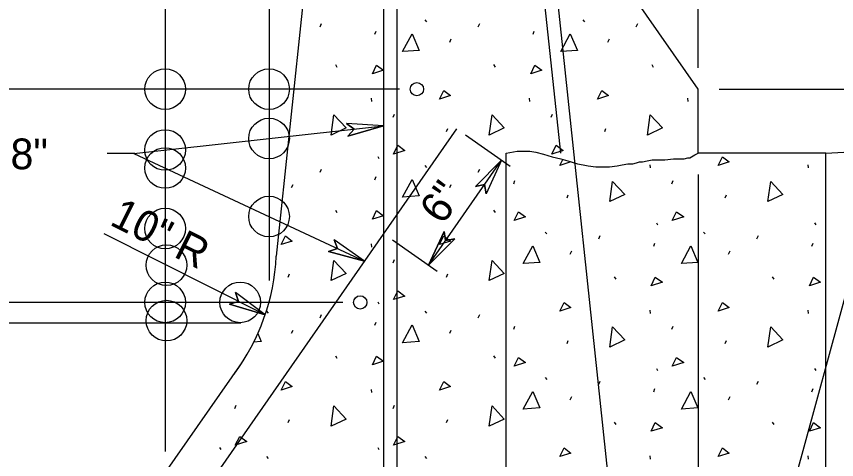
# Model space of a CAD drawing. Extents: x -26.46 to -19.21, y -3.62 to 6.25.
# Drawn here: x -23.781 to -22.178, y 2.816 to 3.682 of the extents above; entities that cross this region are included whole.
import ezdxf

# ---------------------------------------------------------------- set-up
doc = ezdxf.new("R2010")
doc.units = 0
for name, color, linetype in [('ANNO-WOUT', 7, 'Continuous'), ('DETL-DIMS', 7, 'Continuous'), ('DETL-PATT', 7, 'Continuous'), ('Level 10', 7, 'Continuous'), ('Level 12', 7, 'Continuous'), ('SECT-GRND_P', 7, 'Continuous'), ('SUBS-FOOT_P', 7, 'Continuous'), ('SUPR-PARA_P', 7, 'Continuous'), ('SUPR-RFRC', 7, 'Continuous')]:
    doc.layers.add(name, color=color, linetype=linetype)

msp = doc.modelspace()

# ---------------------------------------------------------------- linework, layer by layer
at = {"layer": 'ANNO-WOUT'}
for centre in [(-23.4904, 3.5396), (-23.2873, 3.5396), (-23.2873, 3.4431), (-23.4904, 3.4207), (-23.4904, 3.3855), (-23.2873, 3.2906), (-23.4904, 3.2672), (-23.4878, 3.1956), (-23.4904, 3.1229), (-23.3437, 3.1229), (-23.4878, 3.0872)]:
    msp.add_circle(centre, 0.0397, dxfattribs=at)
at = {"layer": 'DETL-DIMS'}
for p, q in [((-23.0634, 3.4678), (-23.1358, 3.4726)), ((-23.121, 3.4615), (-23.1358, 3.4726)), ((-23.0634, 3.4678), (-23.133, 3.4475)), ((-23.133, 3.4475), (-23.121, 3.4615)), ((-22.8327, 3.4011), (-22.8838, 3.3495)), ((-22.8327, 3.4011), (-22.8632, 3.3351)), ((-22.8838, 3.3495), (-22.8659, 3.3535)), ((-22.8659, 3.3535), (-22.8632, 3.3351)), ((-22.9756, 3.1959), (-22.945, 3.2617)), ((-22.945, 3.2617), (-22.9425, 3.2435)), ((-23.1007, 3.2034), (-23.1601, 3.2452)), ((-23.1533, 3.2279), (-23.1601, 3.2452)), ((-22.9756, 3.1959), (-22.9243, 3.2473)), ((-22.9425, 3.2435), (-22.9243, 3.2473)), ((-23.1708, 3.2223), (-23.1533, 3.2279)), ((-23.1007, 3.2034), (-23.1708, 3.2223)), ((-23.295, 3.0984), (-23.3531, 3.1419)), ((-23.3468, 3.1245), (-23.3531, 3.1419)), ((-23.3645, 3.1194), (-23.3468, 3.1245)), ((-23.295, 3.0984), (-23.3645, 3.1194))]:
    msp.add_line(p, q, dxfattribs=at)
for points in [[(-23.133, 3.4475), (-23.0634, 3.4678), (-23.1358, 3.4726), (-23.121, 3.4615)], [(-22.8838, 3.3495), (-22.8327, 3.4011), (-22.8632, 3.3351), (-22.8659, 3.3535)], [(-22.945, 3.2617), (-22.9756, 3.1959), (-22.9243, 3.2473), (-22.9425, 3.2435)], [(-23.1708, 3.2223), (-23.1007, 3.2034), (-23.1601, 3.2452), (-23.1533, 3.2279)], [(-23.3645, 3.1194), (-23.295, 3.0984), (-23.3531, 3.1419), (-23.3468, 3.1245)]]:
    msp.add_lwpolyline(points, close=True, dxfattribs=at)
at = {"layer": 'DETL-PATT'}
for p, q in [((-22.9829, 3.6748), (-22.9798, 3.6709)), ((-22.6737, 3.6748), (-22.6706, 3.6709)), ((-23.1877, 3.6617), (-23.1847, 3.6678)), ((-22.8786, 3.6617), (-22.8755, 3.6678)), ((-22.5694, 3.6617), (-22.5663, 3.6678)), ((-23.0803, 3.647), (-23.078, 3.6532)), ((-22.7711, 3.647), (-22.7688, 3.6532)), ((-22.9342, 3.6315), (-22.9311, 3.6377)), ((-22.625, 3.6315), (-22.622, 3.6377)), ((-23.1576, 3.5875), (-23.1545, 3.5828)), ((-22.8484, 3.5875), (-22.8453, 3.5828)), ((-22.5392, 3.5875), (-22.5362, 3.5828)), ((-23.088, 3.5218), (-23.0873, 3.5156)), ((-22.7789, 3.5218), (-22.7781, 3.5156)), ((-22.4697, 3.5218), (-22.4689, 3.5156)), ((-23.0447, 3.4847), (-23.0424, 3.4908)), ((-22.7356, 3.4847), (-22.7333, 3.4908)), ((-22.9404, 3.4568), (-22.9381, 3.463)), ((-22.6312, 3.4568), (-22.6289, 3.463)), ((-23.0749, 3.4081), (-23.0726, 3.4043)), ((-22.7187, 3.3903), (-22.7128, 3.4022)), ((-23.1877, 3.3772), (-23.1847, 3.3834)), ((-22.9829, 3.3904), (-22.9798, 3.3865)), ((-22.8786, 3.3772), (-22.8755, 3.3834)), ((-22.5432, 3.3918), (-22.5425, 3.3857)), ((-22.2341, 3.3918), (-22.2333, 3.3857)), ((-23.0803, 3.3625), (-23.078, 3.3687)), ((-23.2434, 3.3471), (-23.2403, 3.3533)), ((-22.9342, 3.3471), (-22.9311, 3.3533)), ((-22.8091, 3.3547), (-22.8068, 3.3609)), ((-22.5, 3.3547), (-22.4976, 3.3609)), ((-22.7048, 3.3269), (-22.7025, 3.3331)), ((-22.3956, 3.3269), (-22.3933, 3.3331)), ((-23.1576, 3.303), (-23.1545, 3.2984)), ((-22.8484, 3.303), (-22.8453, 3.2984)), ((-22.5301, 3.2782), (-22.5278, 3.2744)), ((-22.2209, 3.2782), (-22.2186, 3.2744)), ((-22.7473, 3.2604), (-22.7442, 3.2566)), ((-22.4381, 3.2604), (-22.435, 3.2566)), ((-22.643, 3.2473), (-22.6399, 3.2535)), ((-22.5355, 3.2326), (-22.5332, 3.2388)), ((-22.3338, 3.2473), (-22.3307, 3.2535)), ((-22.2263, 3.2326), (-22.224, 3.2388)), ((-23.088, 3.2373), (-23.0873, 3.2311)), ((-22.6986, 3.2172), (-22.6955, 3.2233)), ((-22.3894, 3.2172), (-22.3863, 3.2233)), ((-23.0447, 3.2002), (-23.0424, 3.2064)), ((-23.2496, 3.1724), (-23.2473, 3.1786)), ((-22.9404, 3.1724), (-22.9381, 3.1786)), ((-22.6128, 3.1731), (-22.6097, 3.1685)), ((-22.3036, 3.1731), (-22.3005, 3.1685)), ((-23.0749, 3.1237), (-23.0726, 3.1198)), ((-23.2921, 3.1059), (-23.289, 3.1021)), ((-23.1877, 3.0928), (-23.1847, 3.099)), ((-22.9829, 3.1059), (-22.9798, 3.1021)), ((-22.8786, 3.0928), (-22.8755, 3.099)), ((-22.5432, 3.1074), (-22.5425, 3.1012)), ((-22.2341, 3.1074), (-22.2333, 3.1012)), ((-23.0803, 3.0781), (-23.078, 3.0843)), ((-23.2434, 3.0626), (-23.2403, 3.0688)), ((-22.9342, 3.0626), (-22.9311, 3.0688)), ((-22.8091, 3.0703), (-22.8068, 3.0765)), ((-22.5, 3.0703), (-22.4976, 3.0765)), ((-22.7048, 3.0425), (-22.7025, 3.0487)), ((-22.3956, 3.0425), (-22.3933, 3.0487)), ((-23.1576, 3.0186), (-23.1545, 3.0139)), ((-22.8484, 3.0186), (-22.8453, 3.0139)), ((-22.5301, 2.9938), (-22.5278, 2.9899)), ((-22.2209, 2.9938), (-22.2186, 2.9899)), ((-22.7473, 2.976), (-22.7442, 2.9721)), ((-22.643, 2.9629), (-22.6399, 2.9691)), ((-22.4381, 2.976), (-22.435, 2.9721)), ((-22.3338, 2.9629), (-22.3307, 2.9691)), ((-23.088, 2.9529), (-23.0873, 2.9467)), ((-22.5355, 2.9482), (-22.5332, 2.9544)), ((-22.2263, 2.9482), (-22.224, 2.9544)), ((-22.6986, 2.9327), (-22.6955, 2.9389)), ((-22.3894, 2.9327), (-22.3863, 2.9389)), ((-23.3539, 2.9158), (-23.3516, 2.922)), ((-23.0447, 2.9158), (-23.0424, 2.922)), ((-23.2496, 2.8879), (-23.2473, 2.8941)), ((-22.9404, 2.8879), (-22.9381, 2.8941)), ((-22.6128, 2.8887), (-22.6097, 2.884)), ((-22.3036, 2.8887), (-22.3005, 2.884)), ((-23.3841, 2.8393), (-23.3818, 2.8354)), ((-23.0749, 2.8393), (-23.0726, 2.8354)), ((-22.5432, 2.823), (-22.5425, 2.8168)), ((-22.2341, 2.823), (-22.2333, 2.8168)), ((-23.2921, 2.8215), (-23.289, 2.8176)), ((-22.9829, 2.8215), (-22.9798, 2.8176))]:
    msp.add_line(p, q, dxfattribs=at)
for points in [[(-23.0262, 3.613), (-23.0076, 3.6477), (-22.9937, 3.6153), (-23.0262, 3.613)], [(-22.717, 3.613), (-22.6985, 3.6477), (-22.6846, 3.6153), (-22.717, 3.613)], [(-23.0849, 3.5697), (-23.0772, 3.5867), (-23.0633, 3.5766), (-23.0849, 3.5697)], [(-22.7758, 3.5697), (-22.768, 3.5867), (-22.7541, 3.5766), (-22.7758, 3.5697)], [(-22.9543, 3.5202), (-22.9458, 3.5372), (-22.9327, 3.5272), (-22.9543, 3.5202)], [(-22.6451, 3.5202), (-22.6366, 3.5372), (-22.6235, 3.5272), (-22.6451, 3.5202)], [(-23.1661, 3.4499), (-23.1607, 3.4893), (-23.1367, 3.4638), (-23.1661, 3.4499)], [(-22.8569, 3.4499), (-22.8515, 3.4893), (-22.8276, 3.4638), (-22.8569, 3.4499)], [(-22.5477, 3.4499), (-22.5423, 3.4893), (-22.5184, 3.4638), (-22.5477, 3.4499)], [(-23.044, 3.4128), (-23.0355, 3.4298), (-23.0216, 3.4197), (-23.044, 3.4128)], [(-22.7348, 3.4128), (-22.7263, 3.4298), (-22.7124, 3.4197), (-22.7348, 3.4128)], [(-22.4095, 3.3903), (-22.401, 3.4073), (-22.3879, 3.3973), (-22.4095, 3.3903)], [(-22.6977, 3.3978), (-22.6971, 3.3973), (-22.7187, 3.3903)], [(-23.0262, 3.3285), (-23.0076, 3.3633), (-22.9937, 3.3308), (-23.0262, 3.3285)], [(-22.6213, 3.32), (-22.6159, 3.3594), (-22.5919, 3.3339), (-22.6213, 3.32)], [(-22.3121, 3.32), (-22.3067, 3.3594), (-22.2828, 3.3339), (-22.3121, 3.32)], [(-23.0849, 3.2852), (-23.0772, 3.3022), (-23.0633, 3.2922), (-23.0849, 3.2852)], [(-22.8084, 3.2829), (-22.7999, 3.2999), (-22.786, 3.2898), (-22.8084, 3.2829)], [(-22.4992, 3.2829), (-22.4907, 3.2999), (-22.4768, 3.2898), (-22.4992, 3.2829)], [(-23.2635, 3.2358), (-23.255, 3.2528), (-23.2418, 3.2427), (-23.2635, 3.2358)], [(-22.9543, 3.2358), (-22.9458, 3.2528), (-22.9327, 3.2427), (-22.9543, 3.2358)], [(-22.7906, 3.1986), (-22.772, 3.2334), (-22.7581, 3.2009), (-22.7906, 3.1986)], [(-22.4814, 3.1986), (-22.4629, 3.2334), (-22.4489, 3.2009), (-22.4814, 3.1986)], [(-23.1661, 3.1654), (-23.1607, 3.2049), (-23.1367, 3.1793), (-23.1661, 3.1654)], [(-22.8569, 3.1654), (-22.8515, 3.2049), (-22.8276, 3.1793), (-22.8569, 3.1654)], [(-22.5402, 3.1553), (-22.5324, 3.1723), (-22.5185, 3.1623), (-22.5402, 3.1553)], [(-22.231, 3.1553), (-22.2233, 3.1723), (-22.2093, 3.1623), (-22.231, 3.1553)], [(-23.044, 3.1283), (-23.0355, 3.1453), (-23.0216, 3.1353), (-23.044, 3.1283)], [(-22.7187, 3.1059), (-22.7102, 3.1229), (-22.6971, 3.1128), (-22.7187, 3.1059)], [(-22.4095, 3.1059), (-22.401, 3.1229), (-22.3879, 3.1128), (-22.4095, 3.1059)], [(-23.0262, 3.0441), (-23.0076, 3.0789), (-22.9937, 3.0464), (-23.0262, 3.0441)], [(-22.6213, 3.0355), (-22.6159, 3.0749), (-22.5919, 3.0494), (-22.6213, 3.0355)], [(-22.3121, 3.0355), (-22.3067, 3.0749), (-22.2828, 3.0494), (-22.3121, 3.0355)], [(-23.3095, 3.0618), (-23.3029, 3.0464), (-23.3175, 3.0454)], [(-23.0849, 3.0008), (-23.0772, 3.0178), (-23.0633, 3.0078), (-23.0849, 3.0008)], [(-22.8084, 2.9984), (-22.7999, 3.0154), (-22.786, 3.0054), (-22.8084, 2.9984)], [(-22.4992, 2.9984), (-22.4907, 3.0154), (-22.4768, 3.0054), (-22.4992, 2.9984)], [(-23.2635, 2.9513), (-23.255, 2.9683), (-23.2418, 2.9583), (-23.2635, 2.9513)], [(-22.9543, 2.9513), (-22.9458, 2.9683), (-22.9327, 2.9583), (-22.9543, 2.9513)], [(-22.7906, 2.9142), (-22.772, 2.949), (-22.7581, 2.9165), (-22.7906, 2.9142)], [(-22.4814, 2.9142), (-22.4629, 2.949), (-22.4489, 2.9165), (-22.4814, 2.9142)], [(-23.1661, 2.881), (-23.1607, 2.9204), (-23.1367, 2.8949), (-23.1661, 2.881)], [(-22.8569, 2.881), (-22.8515, 2.9204), (-22.8276, 2.8949), (-22.8569, 2.881)], [(-22.5402, 2.8709), (-22.5324, 2.8879), (-22.5185, 2.8778), (-22.5402, 2.8709)], [(-22.231, 2.8709), (-22.2233, 2.8879), (-22.2093, 2.8778), (-22.231, 2.8709)], [(-23.3532, 2.8439), (-23.3446, 2.8609), (-23.3307, 2.8508), (-23.3532, 2.8439)], [(-23.044, 2.8439), (-23.0355, 2.8609), (-23.0216, 2.8508), (-23.044, 2.8439)], [(-22.7187, 2.8214), (-22.7102, 2.8384), (-22.6971, 2.8284), (-22.7187, 2.8214)], [(-22.4095, 2.8214), (-22.401, 2.8384), (-22.3879, 2.8284), (-22.4095, 2.8214)]]:
    msp.add_lwpolyline(points, dxfattribs=at)
at = {"layer": 'Level 10'}
for p, q in [((-23.4904, 6.1854), (-23.4904, 2.8312)), ((-22.4488, 3.5812), (-22.4488, 6.1854)), ((-23.2873, 5.6854), (-23.2873, 3.1655)), ((-23.0321, 3.5396), (-24.5112, 3.5396)), ((-22.4072, 3.5396), (-20.678, 3.5396)), ((-23.5514, 3.414), (-23.0634, 3.4678)), ((-22.9034, 3.4503), (-22.8157, 3.3892)), ((-23.5495, 3.414), (-23.6034, 3.414)), ((-23.5514, 3.414), (-23.1007, 3.2034)), ((-22.9756, 3.1959), (-22.8327, 3.4011)), ((-22.4488, 3.373), (-22.4488, 1.4771)), ((-23.295, 3.0984), (-23.6094, 3.2568)), ((-23.0463, 3.2451), (-22.9585, 3.184)), ((-22.1526, 3.166), (-22.2901, 2.6648)), ((-23.143, 3.1229), (-24.5112, 3.1229)), ((-24.7603, 3.0831), (-23.3422, 3.0831))]:
    msp.add_line(p, q, dxfattribs=at)
at = {"layer": 'SECT-GRND_P'}
msp.add_line((-22.1988, 3.4146), (-21.4484, 3.4565), dxfattribs=at)
at = {"layer": 'SUBS-FOOT_P'}
for p, q in [((-22.8238, 2.6646), (-22.8238, 3.4146)), ((-22.1988, 3.4146), (-22.4488, 3.4146)), ((-22.1988, 1.9979), (-22.1988, 3.4146))]:
    msp.add_line(p, q, dxfattribs=at)
msp.add_lwpolyline([(-22.8238, 3.4146), (-22.802, 3.4185), (-22.7907, 3.4185), (-22.785, 3.4185), (-22.7774, 3.4185), (-22.766, 3.4166), (-22.7509, 3.4128), (-22.7338, 3.4071), (-22.7167, 3.4033), (-22.7035, 3.3995), (-22.6845, 3.3938), (-22.6732, 3.3919), (-22.6637, 3.39), (-22.6485, 3.3881), (-22.6372, 3.3881), (-22.622, 3.3881), (-22.6068, 3.39), (-22.5974, 3.3919), (-22.586, 3.3938), (-22.5765, 3.3938), (-22.5689, 3.3957), (-22.5632, 3.3976), (-22.5576, 3.3976), (-22.5481, 3.3995), (-22.5386, 3.4014), (-22.5253, 3.4014), (-22.514, 3.4014), (-22.4969, 3.4033), (-22.4912, 3.4033), (-22.4799, 3.4033), (-22.4761, 3.4033), (-22.4685, 3.4052), (-22.4647, 3.4052), (-22.4552, 3.411), (-22.4488, 3.4146)], dxfattribs=at)
at = {"layer": 'SUPR-PARA_P'}
for p, q in [((-23.1467, 4.4146), (-23.2734, 3.2131)), ((-22.4488, 3.5396), (-22.5992, 3.7556)), ((-22.4488, 3.4146), (-22.4488, 3.5396)), ((-23.4904, 2.7896), (-23.34, 3.0056))]:
    msp.add_line(p, q, dxfattribs=at)
msp.add_arc((-23.6896, 3.2322), 0.4167, 323.2474, 357.3682, dxfattribs=at)
at = {"layer": 'SUPR-RFRC'}
for p, q in [((-22.8335, 4.5099), (-22.7179, 3.4146)), ((-22.8076, 4.5126), (-22.5561, 2.1286)), ((-23.0634, 3.7687), (-23.0634, 2.1229)), ((-23.0373, 3.7687), (-23.0373, 2.6646)), ((-23.4071, 2.7634), (-22.9205, 3.4622))]:
    msp.add_line(p, q, dxfattribs=at)
for centre in [(-22.9983, 3.5396), (-23.1091, 3.1229)]:
    msp.add_circle(centre, 0.013, dxfattribs=at)

# ---------------------------------------------------------------- texts
at = {"layer": 'Level 12'}
msp.add_text('#5 @ 8"', height=0.06001, dxfattribs=at).set_placement((-24.0079, 3.3831))
for s, rotation, p in [('6"', 55.1455, (-22.9476, 3.2725)), ('10" R', 333.3856, (-23.6011, 3.2756))]:
    msp.add_text(s, height=0.06001, rotation=rotation, dxfattribs=at).set_placement(p)

doc.saveas('drawing.dxf')
